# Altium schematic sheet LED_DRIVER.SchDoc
size A3; SheetNumber: 12; SheetTotal: 16
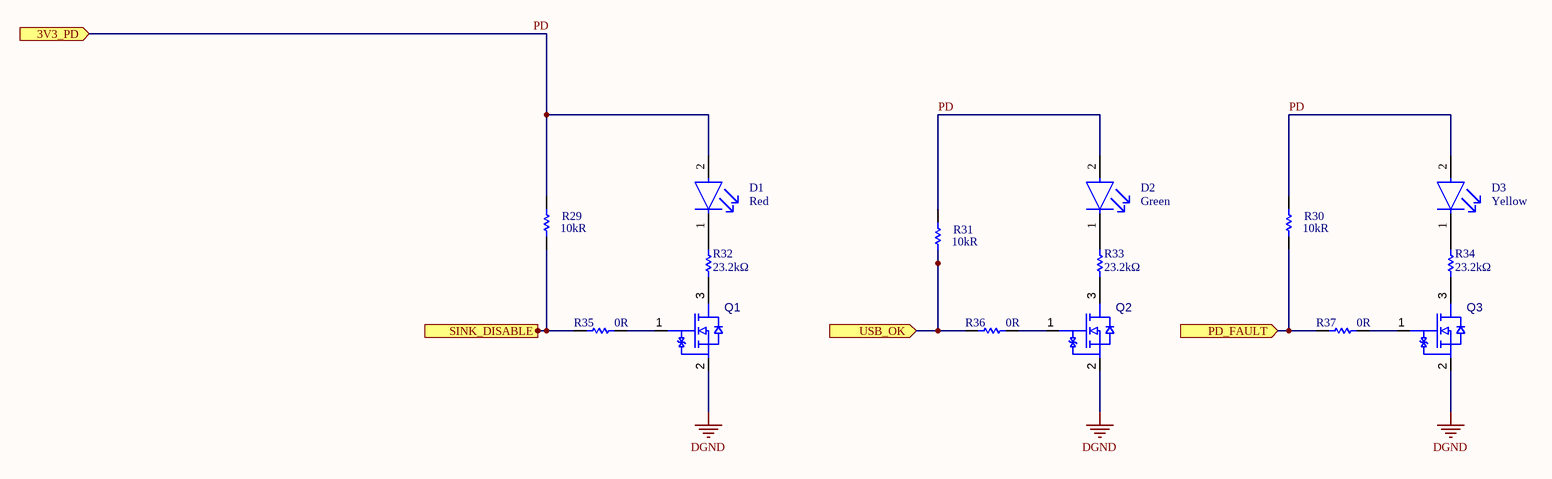
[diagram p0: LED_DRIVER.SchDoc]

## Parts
D1  value Red  [FP-VLMO1500-GS08-MFG]  (hidden comment: VLMS1500-GS08)
D2  value Green  [FP-VLMO1500-GS08-MFG]  (hidden comment: VLMG1500-GS08)
D3  value Yellow  [FP-VLMO1500-GS08-MFG]  (hidden comment: VLMY1500-GS08)
Q1  RUM002N05T2L  [ROHM-SOT723-3_V]  (value not drawn)
Q2  RUM002N05T2L  [ROHM-SOT723-3_V]  (value not drawn)
Q3  RUM002N05T2L  [ROHM-SOT723-3_V]  (value not drawn)
R29  value 10kR  [RESC1005X40X25LL10T10]  (hidden comment: RK73H1ETTP1002F)
R30  value 10kR  [RESC1005X40X25LL10T10]  (hidden comment: RK73H1ETTP1002F)
R31  value 10kR  [RESC1005X40X25LL10T10]  (hidden comment: RK73H1ETTP1002F)
R32  value 23.2kΩ  [RESC1005X40X25LL10T10]  (hidden comment: RK73H1ETTP2322F)
R33  value 23.2kΩ  [RESC1005X40X25LL10T10]  (hidden comment: RK73H1ETTP2322F)
R34  value 23.2kΩ  [RESC1005X40X25LL10T10]  (hidden comment: RK73H1ETTP2322F)
R35  value 0R  [FP-RK73Z1E-IPC_B]  (hidden comment: RK73Z1ETTP)
R36  value 0R  [FP-RK73Z1E-IPC_B]  (hidden comment: RK73Z1ETTP)
R37  value 0R  [FP-RK73Z1E-IPC_B]  (hidden comment: RK73Z1ETTP)

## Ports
3V3_PD (in), PD_FAULT (in), SINK_DISABLE (in), USB_OK (in)

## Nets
DGND: Q1.2(S) Q2.2(S) Q3.2(S)
PD: D1.2(A) D2.2(A) D3.2(A) R29.1 R30.1 R31.1 ; port 3V3_PD
PD_FAULT: R30.2 R37.1 ; port PD_FAULT
SINK_DISABLE: R29.2 R35.1 ; port SINK_DISABLE
USB_OK: R31.2 R36.1 ; port USB_OK
NetD1_1: D1.1(C) R32.2
NetD2_1: D2.1(C) R33.2
NetD3_1: D3.1(C) R34.2
NetQ1_1: Q1.1(G) R35.2
NetQ1_3: Q1.3(D) R32.1
NetQ2_1: Q2.1(G) R36.2
NetQ2_3: Q2.3(D) R33.1
NetQ3_1: Q3.1(G) R37.2
NetQ3_3: Q3.3(D) R34.1

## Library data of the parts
D1 = CMP-00030-24098164-1: RED 0402 VLMx1500; Luminous Intensity: 90mcd; Dominant Wavelength: 605nm; Forward Voltage: 2V; Test Current: 20mA; Lens Style: Rectangular, Square; Reverse Voltage: 5V; Power Rating: 75mW; Illumination Color: Orange; Viewing Angle: 130°; Number of LEDs: 1
D2 = CMP-00030-24098164-1: GREEN 0402 VLMx1500; Luminous Intensity: 90mcd; Dominant Wavelength: 605nm; Forward Voltage: 2V; Test Current: 20mA; Lens Style: Rectangular, Square; Reverse Voltage: 5V; Power Rating: 75mW; Illumination Color: Orange; Viewing Angle: 130°; Number of LEDs: 1
D3 = CMP-00030-24098164-1: YELLOW 0402 VLMx1500; Luminous Intensity: 90mcd; Dominant Wavelength: 605nm; Forward Voltage: 2V; Test Current: 20mA; Lens Style: Rectangular, Square; Reverse Voltage: 5V; Power Rating: 75mW; Illumination Color: Orange; Viewing Angle: 130°; Number of LEDs: 1
Q1-Q3 = CMP-013-00026-2: Nch Small Signal MOSFET, 50 V, 200 mA, 3-Pin SOT723, RoHS, Tape and Reel; Vgs(th) (Max) @ Id: 1V@1mA
R29-R31 = CMP-x00150-1: Fixed Resistor, Metal Glaze/thick Film, 0.1W, 10000ohm, 75V, 1% +/-Tol, 100ppm/Cel, Surface Mount, 0402
R32-R34 = CMP-009-00229-1: Fixed Resistor, Metal Glaze/thick Film, 0.1W, 23200ohm, 75V, 1% +/-Tol, 100ppm/Cel, Surface Mount, 0402; Vendor: TTI; Rating: 1/10W
R35-R37 = CMP-x00147-1: Metal Glaze/thick Film, 0ohm, Surface Mount, 0402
